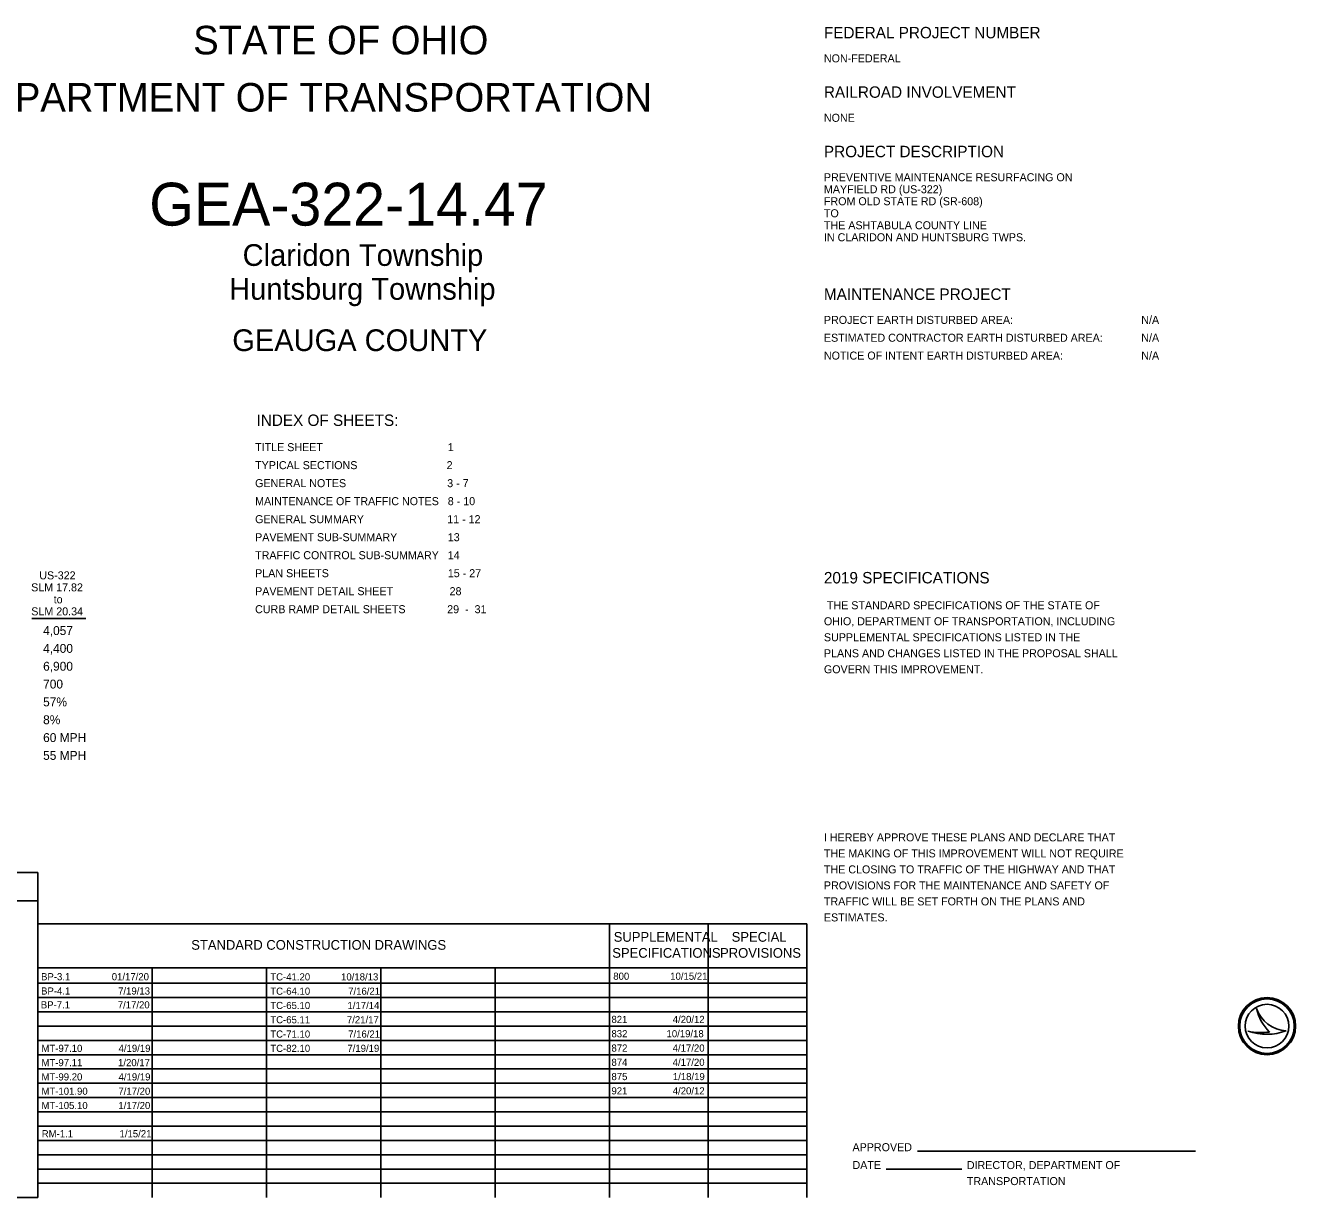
# Model space of a CAD drawing. Extents: x -17.5 to 72.9, y -57.8 to 32.3.
# Drawn here: x 50.67 to 72.89, y -57.83 to -37.32 of the extents above; entities that cross this region are included whole.
import ezdxf

# ---------------------------------------------------------------- set-up
doc = ezdxf.new("R2010")
doc.units = 0
doc.layers.add('SH_Data', color=7, linetype='Continuous')
doc.layers.add('SH_Text', color=7, linetype='Continuous')

msp = doc.modelspace()

# ---------------------------------------------------------------- linework, layer by layer
at = {"layer": 'SH_Data'}
for p, q in [((46.636, -52.141), (50.886, -52.141)), ((50.886, -57.829), (50.886, -52.141)), ((46.636, -52.635), (50.886, -52.635)), ((50.886, -53.037), (64.336, -53.037)), ((50.886, -57.829), (50.886, -53.037)), ((50.886, -57.829), (50.886, -53.037)), ((60.886, -57.829), (60.886, -53.037)), ((62.611, -57.829), (62.611, -53.037)), ((64.336, -57.829), (64.336, -53.037)), ((50.886, -53.808), (64.336, -53.808)), ((52.886, -57.829), (52.886, -53.808)), ((54.886, -57.829), (54.886, -53.808)), ((56.886, -57.829), (56.886, -53.808)), ((58.886, -57.829), (58.886, -53.808)), ((50.886, -54.079), (64.336, -54.079)), ((50.886, -54.329), (64.336, -54.329)), ((50.886, -54.579), (64.336, -54.579)), ((72.204, -54.519), (72.204, -54.519)), ((50.886, -54.829), (64.336, -54.829)), ((50.886, -55.079), (64.336, -55.079)), ((72.053, -54.919), (72.053, -54.919)), ((72.723, -54.91), (72.723, -54.91)), ((50.886, -55.329), (64.336, -55.329)), ((50.886, -55.579), (64.336, -55.579)), ((50.886, -55.829), (64.336, -55.829)), ((50.886, -56.079), (64.336, -56.079)), ((50.886, -56.329), (64.336, -56.329)), ((50.886, -56.579), (64.336, -56.579)), ((50.886, -56.829), (64.336, -56.829)), ((50.886, -57.079), (64.336, -57.079)), ((66.271, -57.017), (71.136, -57.017)), ((50.886, -57.329), (64.336, -57.329)), ((65.727, -57.329), (67.05, -57.329)), ((50.886, -57.579), (64.336, -57.579)), ((46.636, -57.829), (50.886, -57.829))]:
    msp.add_line(p, q, dxfattribs=at)
for radius in [0.5, 0.477, 0.477, 0.382]:
    msp.add_circle((72.386, -54.829), radius, dxfattribs=at)
for centre, radius, start, end in [((72.752, -54.331), 0.58, 198.9257, 198.9319), ((72.983, -54.359), 0.796, 191.6379, 191.6421), ((72.752, -54.331), 0.58, 198.9319, 267.1657), ((72.983, -54.359), 0.796, 191.6421, 226.0947), ((72.376, -53.959), 1.013, 251.4576, 290.0832), ((72.284, -53.675), 1.266, 259.4964, 259.4995), ((72.376, -53.959), 1.013, 251.4527, 251.4576), ((72.284, -53.675), 1.266, 259.4995, 276.6672)]:
    msp.add_arc(centre, radius, start, end, dxfattribs=at)
at = {"layer": 'SH_Text'}
msp.add_line((50.782, -47.696), (51.728, -47.696), dxfattribs=at)

# ---------------------------------------------------------------- texts
at = {"layer": 'SH_Data'}
for s, height, p in [('MAINTENANCE PROJECT', 0.2, (64.636, -42.124)), ('PROJECT EARTH DISTURBED AREA:', 0.14, (64.636, -42.544)), ('N/A', 0.14, (70.187, -42.544)), ('ESTIMATED CONTRACTOR EARTH DISTURBED AREA:', 0.14, (64.636, -42.856)), ('N/A', 0.14, (70.187, -42.856)), ('NOTICE OF INTENT EARTH DISTURBED AREA:', 0.14, (64.636, -43.168)), ('N/A', 0.14, (70.187, -43.168)), ('4,057', 0.156, (50.979, -47.987)), ('4,400', 0.156, (50.979, -48.299)), ('6,900', 0.156, (50.979, -48.611)), ('700', 0.156, (50.979, -48.923)), ('57%', 0.156, (50.979, -49.235)), ('8%', 0.156, (50.979, -49.547)), ('60 MPH', 0.156, (50.979, -49.859)), ('55 MPH', 0.156, (50.979, -50.171)), ('I HEREBY APPROVE THESE PLANS AND DECLARE THAT', 0.14, (64.636, -51.597)), ('THE MAKING OF THIS IMPROVEMENT WILL NOT REQUIRE', 0.14, (64.636, -51.877)), ('THE CLOSING TO TRAFFIC OF THE HIGHWAY AND THAT', 0.14, (64.636, -52.157)), ('PROVISIONS FOR THE MAINTENANCE AND SAFETY OF', 0.14, (64.636, -52.437)), ('TRAFFIC WILL BE SET FORTH ON THE PLANS AND', 0.14, (64.636, -52.717)), ('ESTIMATES.', 0.14, (64.636, -52.997))]:
    msp.add_text(s, height=height, dxfattribs=at).set_placement(p)
at = {"layer": 'SH_Text'}
for s, height, p in [('STATE OF OHIO', 0.5, (53.604, -37.829)), ('FEDERAL PROJECT NUMBER', 0.2, (64.636, -37.548)), ('NON-FEDERAL', 0.14, (64.636, -37.968)), ('DEPARTMENT OF TRANSPORTATION', 0.5, (49.556, -38.829)), ('RAILROAD INVOLVEMENT', 0.2, (64.636, -38.588)), ('NONE', 0.14, (64.636, -39.008)), ('PROJECT DESCRIPTION', 0.2, (64.636, -39.628)), ('PREVENTIVE MAINTENANCE RESURFACING ON ', 0.14, (64.636, -40.048)), ('GEA-322-14.47', 0.75, (52.835, -40.824)), ('MAYFIELD RD (US-322) ', 0.14, (64.636, -40.258)), ('FROM OLD STATE RD (SR-608) ', 0.14, (64.636, -40.468)), ('TO ', 0.14, (64.636, -40.678)), ('THE ASHTABULA COUNTY LINE ', 0.14, (64.636, -40.888)), ('IN CLARIDON AND HUNTSBURG TWPS. ', 0.14, (64.636, -41.098)), ('Claridon Township', 0.38, (54.469, -41.529)), ('Huntsburg Township', 0.38, (54.233, -42.121)), ('GEAUGA COUNTY', 0.38, (54.288, -43.019)), ('INDEX OF SHEETS:', 0.2, (54.712, -44.329)), ('TITLE SHEET                                          1', 0.14, (54.687, -44.77)), ('TYPICAL SECTIONS                              2', 0.14, (54.687, -45.085)), ('GENERAL NOTES                                  3 - 7', 0.14, (54.687, -45.4)), ('MAINTENANCE OF TRAFFIC NOTES   8 - 10', 0.14, (54.687, -45.715)), ('GENERAL SUMMARY                            11 - 12', 0.14, (54.687, -46.03)), ('PAVEMENT SUB-SUMMARY                 13', 0.14, (54.687, -46.345)), ('TRAFFIC CONTROL SUB-SUMMARY   14', 0.14, (54.687, -46.66)), ('US-322', 0.14, (50.912, -47.013)), ('PLAN SHEETS                                        15 - 27', 0.14, (54.687, -46.975)), ('SLM 17.82', 0.14, (50.77, -47.223)), ('2019 SPECIFICATIONS', 0.2, (64.636, -47.084)), ('to', 0.14, (51.164, -47.433)), ('PAVEMENT DETAIL SHEET                   28', 0.14, (54.687, -47.29)), ('SLM 20.34', 0.14, (50.772, -47.643)), ('CURB RAMP DETAIL SHEETS              29  -  31', 0.14, (54.687, -47.605)), (' THE STANDARD SPECIFICATIONS OF THE STATE OF', 0.14, (64.636, -47.536)), ('OHIO, DEPARTMENT OF TRANSPORTATION, INCLUDING', 0.14, (64.636, -47.816)), ('SUPPLEMENTAL SPECIFICATIONS LISTED IN THE', 0.14, (64.636, -48.096)), ('PLANS AND CHANGES LISTED IN THE PROPOSAL SHALL', 0.14, (64.636, -48.376)), ('GOVERN THIS IMPROVEMENT.', 0.14, (64.636, -48.656)), ('STANDARD CONSTRUCTION DRAWINGS', 0.17, (53.57, -53.493)), ('SUPPLEMENTAL', 0.17, (60.96, -53.353)), ('SPECIAL', 0.17, (63.023, -53.353)), ('SPECIFICATIONS', 0.17, (60.934, -53.633)), ('PROVISIONS', 0.17, (62.82, -53.633)), ('BP-3.1', 0.125, (50.943, -54.027)), ('01/17/20', 0.125, (52.18, -54.027)), ('TC-41.20', 0.125, (54.953, -54.03)), ('10/18/13', 0.125, (56.191, -54.03)), ('800', 0.125, (60.952, -54.018)), ('10/15/21', 0.125, (61.948, -54.018)), ('BP-4.1', 0.125, (50.943, -54.277)), ('7/19/13', 0.125, (52.291, -54.277)), ('TC-64.10', 0.125, (54.953, -54.28)), ('7/16/21', 0.125, (56.315, -54.28)), ('BP-7.1', 0.125, (50.939, -54.519)), ('7/17/20', 0.125, (52.285, -54.519)), ('TC-65.10', 0.125, (54.953, -54.53)), ('1/17/14', 0.125, (56.303, -54.53)), ('TC-65.11', 0.125, (54.953, -54.78)), ('7/21/17', 0.125, (56.293, -54.78)), ('821', 0.125, (60.92, -54.774)), ('4/20/12', 0.125, (61.992, -54.774)), ('TC-71.10', 0.125, (54.953, -55.03)), ('7/16/21', 0.125, (56.315, -55.03)), ('832', 0.125, (60.92, -55.024)), ('10/19/18', 0.125, (61.883, -55.024)), ('MT-97.10', 0.125, (50.95, -55.28)), ('4/19/19', 0.125, (52.299, -55.28)), ('TC-82.10', 0.125, (54.953, -55.28)), ('7/19/19', 0.125, (56.301, -55.28)), ('872', 0.125, (60.92, -55.275)), ('4/17/20', 0.125, (61.991, -55.275)), ('MT-97.11', 0.125, (50.95, -55.53)), ('1/20/17', 0.125, (52.29, -55.53)), ('874', 0.125, (60.92, -55.524)), ('4/17/20', 0.125, (61.991, -55.524)), ('MT-99.20', 0.125, (50.95, -55.78)), ('4/19/19', 0.125, (52.299, -55.78)), ('875', 0.125, (60.92, -55.774)), ('1/18/19', 0.125, (61.994, -55.774)), ('MT-101.90', 0.125, (50.95, -56.03)), ('7/17/20', 0.125, (52.296, -56.03)), ('921', 0.125, (60.92, -56.024)), ('4/20/12', 0.125, (61.992, -56.024)), ('MT-105.10', 0.125, (50.95, -56.28)), ('1/17/20', 0.125, (52.296, -56.28)), ('RM-1.1', 0.125, (50.955, -56.774)), ('1/15/21', 0.125, (52.316, -56.774)), ('APPROVED', 0.14, (65.136, -57.017)), ('DATE', 0.14, (65.136, -57.329)), ('DIRECTOR, DEPARTMENT OF', 0.14, (67.136, -57.33)), ('TRANSPORTATION', 0.14, (67.136, -57.61))]:
    msp.add_text(s, height=height, dxfattribs=at).set_placement(p)

doc.saveas('drawing.dxf')
